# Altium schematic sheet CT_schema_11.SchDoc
size 387 x 385 mm
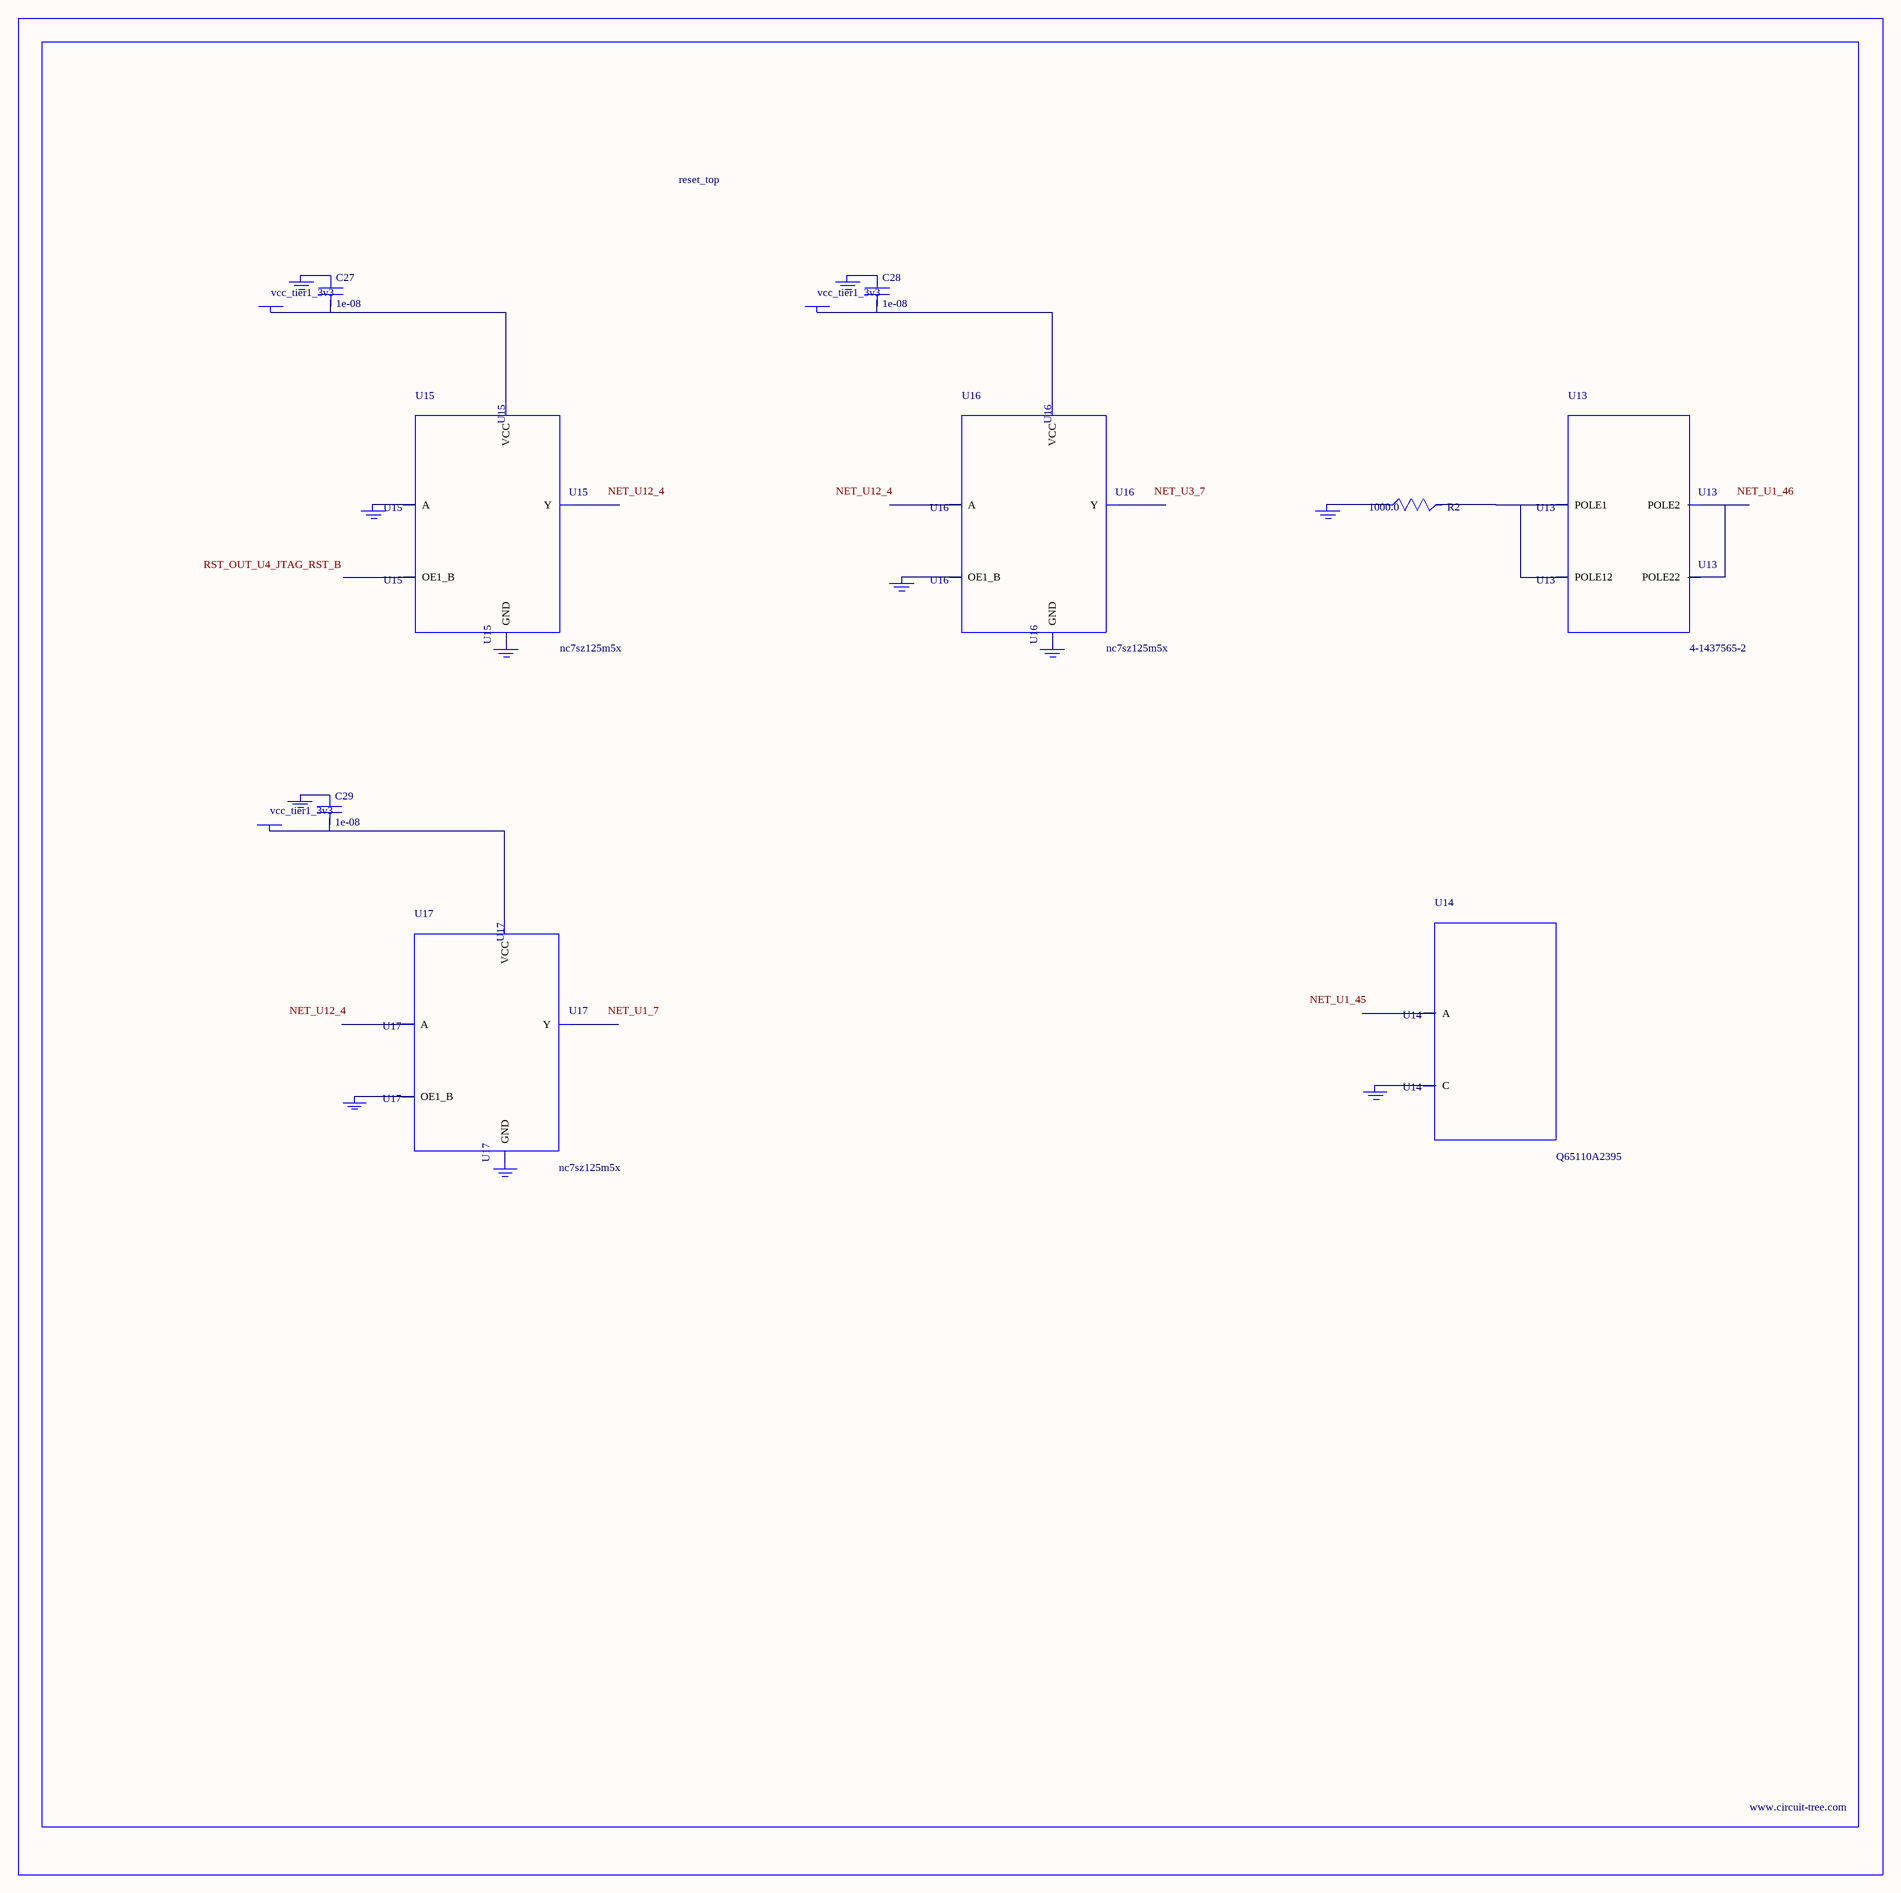
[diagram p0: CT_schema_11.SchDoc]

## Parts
BORDER10  (no value)
C27  1e-08  [C0402]
C28  1e-08  [C0402]
C29  1e-08  [C0402]
GND_INSTANCE_10_0  (no value)
GND_INSTANCE_10_1  (no value)
GND_INSTANCE_10_2  (no value)
GND_INSTANCE_10_3  (no value)
GND_INSTANCE_10_4  (no value)
GND_INSTANCE_10_5  (no value)
GND_INSTANCE_10_6  (no value)
GND_INSTANCE_10_7  (no value)
GND_INSTANCE_10_8  (no value)
GND_INSTANCE_10_9  (no value)
GND_INSTANCE_10_10  (no value)
POWER_INSTANCE_10_0  vcc_tier1_3v3
POWER_INSTANCE_10_1  vcc_tier1_3v3
POWER_INSTANCE_10_2  vcc_tier1_3v3
R2  1000.0  [R0603]
U13  4-1437565-2  [SW_4-1437565-2]
U14  Q65110A2395  [LGM67K-G1J2-24-Z]
U15  nc7sz125m5x  [NC7SZ125M5X]
U16  nc7sz125m5x  [NC7SZ125M5X]
U17  nc7sz125m5x  [NC7SZ125M5X]

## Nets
NetC27_1: C27.1 GND_INSTANCE_10_2.0(GND)
NetC27_2: C27.2 POWER_INSTANCE_10_0.0(PWR) U15.5(VCC)
NetC28_1: C28.1 GND_INSTANCE_10_5.0(GND)
NetC28_2: C28.2 POWER_INSTANCE_10_1.0(PWR) U16.5(VCC)
NetC29_1: C29.1 GND_INSTANCE_10_8.0(GND)
NetC29_2: C29.2 POWER_INSTANCE_10_2.0(PWR) U17.5(VCC)
NetGND_INSTANCE_10_0_0: GND_INSTANCE_10_0.0(GND) R2.1
NetGND_INSTANCE_10_1_0: GND_INSTANCE_10_1.0(GND) U14.C
NetGND_INSTANCE_10_3_0: GND_INSTANCE_10_3.0(GND) U15.2(A)
NetGND_INSTANCE_10_4_0: GND_INSTANCE_10_4.0(GND) U15.3(GND)
NetGND_INSTANCE_10_6_0: GND_INSTANCE_10_6.0(GND) U16.1(OE1_B)
NetGND_INSTANCE_10_7_0: GND_INSTANCE_10_7.0(GND) U16.3(GND)
NetGND_INSTANCE_10_9_0: GND_INSTANCE_10_9.0(GND) U17.1(OE1_B)
NetGND_INSTANCE_10_10_0: GND_INSTANCE_10_10.0(GND) U17.3(GND)
NetR2_2: R2.2 U13.1(POLE1) U13.2(POLE12)
NetU13_3: U13.3(POLE2) U13.4(POLE22)

Not connected (* = marked no-connect by the designer): U14 A; U15 1(OE1_B) 4(Y); U16 2(A) 4(Y); U17 2(A) 4(Y)

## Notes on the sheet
- Labels drawn without touching a wire or pin: NET_U1_7, NET_U1_45, NET_U1_46, NET_U3_7, NET_U12_4, RST_OUT_U4_JTAG_RST_B

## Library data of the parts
BORDER10 = BORDER_PAGE10
C27-C29 = C0402C103K3RAC
GND_INSTANCE_10_0-GND_INSTANCE_10_10 = GND
POWER_INSTANCE_10_0-POWER_INSTANCE_10_2 = PWR
R2 = RC0603JR-071KL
